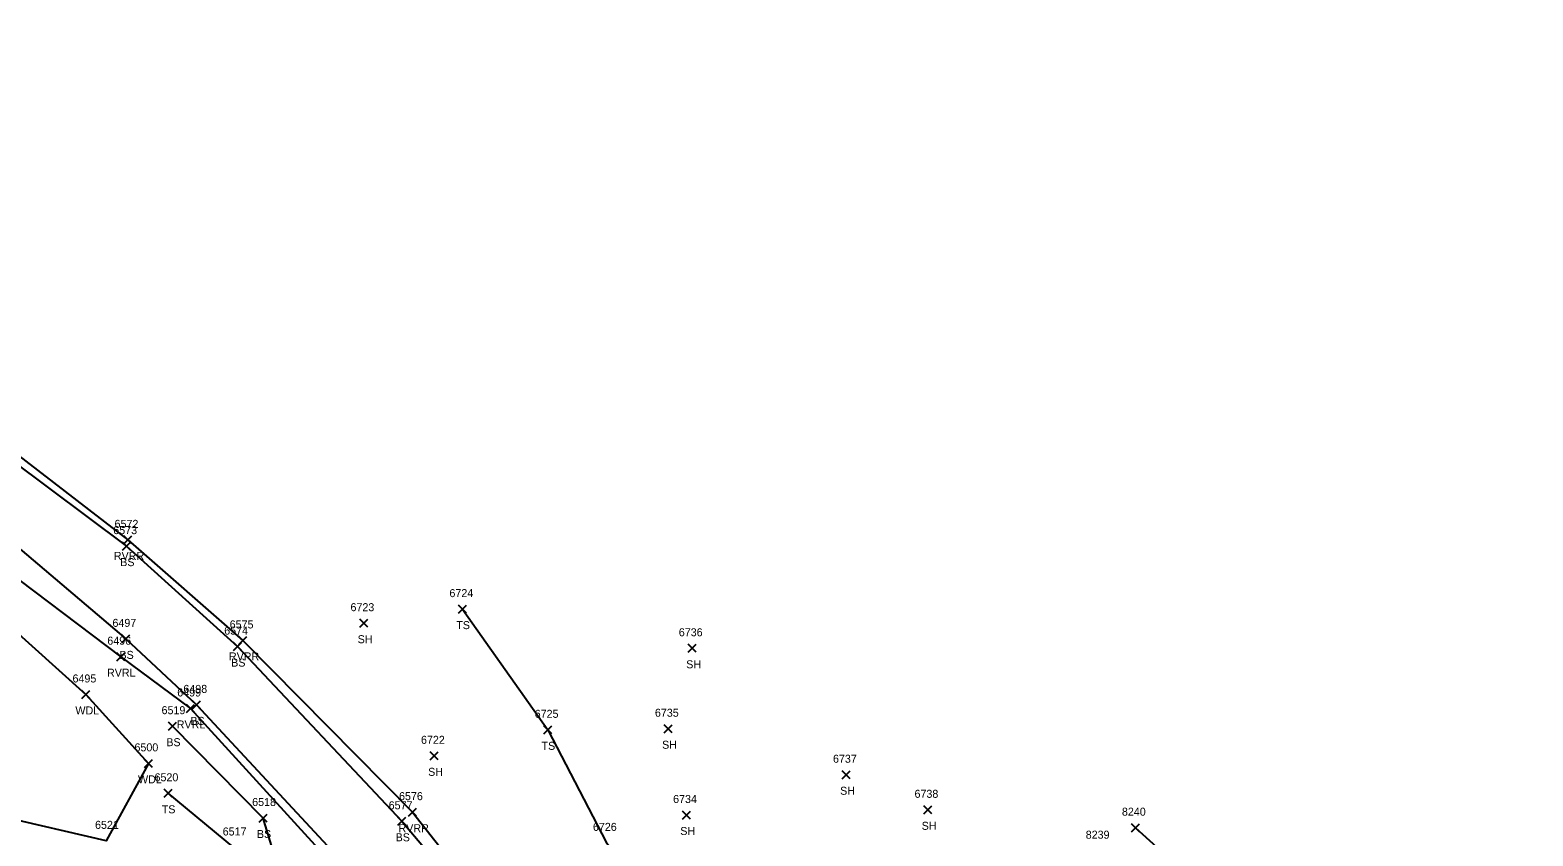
# Model space of a CAD drawing. Extents: x 1588028 to 1589597, y 137576 to 138176.
# Drawn here: x 1588774.4 to 1589149.9, y 137969.2 to 138170.6 of the extents above; entities that cross this region are included whole.
import ezdxf

# ---------------------------------------------------------------- set-up
doc = ezdxf.new("R2010")
doc.units = 0
for name, color, linetype in [('D_I', 7, 'Continuous'), ('L_A', 7, 'Continuous'), ('L_I', 7, 'Continuous'), ('L_TIC', 7, 'Continuous'), ('LAWA', 7, 'Continuous'), ('LAWE', 7, 'Continuous'), ('LELB', 7, 'Continuous')]:
    doc.layers.add(name, color=color, linetype=linetype)

msp = doc.modelspace()

# ---------------------------------------------------------------- linework, layer by layer
at = {"layer": 'L_TIC'}
for points in [[(1588797.46, 138040.61), (1588799.46, 138042.61)], [(1588799.46, 138040.61), (1588797.46, 138042.61)], [(1588797.8, 138042.18), (1588799.8, 138044.18)], [(1588799.8, 138042.18), (1588797.8, 138044.18)], [(1588881.47, 138024.87), (1588883.47, 138026.87)], [(1588883.47, 138024.87), (1588881.47, 138026.87)], [(1588856.75, 138021.35), (1588858.75, 138023.35)], [(1588858.75, 138021.35), (1588856.75, 138023.35)], [(1588797.27, 138017.43), (1588799.27, 138019.43)], [(1588799.27, 138017.43), (1588797.27, 138019.43)], [(1588825.19, 138015.5), (1588827.19, 138017.5)], [(1588827.19, 138015.5), (1588825.19, 138017.5)], [(1588826.56, 138017.04), (1588828.56, 138019.04)], [(1588828.56, 138017.04), (1588826.56, 138019.04)], [(1588938.84, 138015.08), (1588940.84, 138017.08)], [(1588940.84, 138015.08), (1588938.84, 138017.08)], [(1588796.04, 138012.98), (1588798.04, 138014.98)], [(1588798.04, 138012.98), (1588796.04, 138014.98)], [(1588787.28, 138003.54), (1588789.28, 138005.54)], [(1588789.28, 138003.54), (1588787.28, 138005.54)], [(1588813.47, 138000.04), (1588815.47, 138002.04)], [(1588815.47, 138000.04), (1588813.47, 138002.04)], [(1588814.99, 138000.93), (1588816.99, 138002.93)], [(1588816.99, 138000.93), (1588814.99, 138002.93)], [(1588808.98, 137995.61), (1588810.98, 137997.61)], [(1588810.98, 137995.61), (1588808.98, 137997.61)], [(1588902.77, 137994.7), (1588904.77, 137996.7)], [(1588904.77, 137994.7), (1588902.77, 137996.7)], [(1588932.82, 137994.97), (1588934.82, 137996.97)], [(1588934.82, 137994.97), (1588932.82, 137996.97)], [(1588874.37, 137988.2), (1588876.37, 137990.2)], [(1588876.37, 137988.2), (1588874.37, 137990.2)], [(1588802.93, 137986.32), (1588804.93, 137988.32)], [(1588804.93, 137986.32), (1588802.93, 137988.32)], [(1588977.32, 137983.47), (1588979.32, 137985.47)], [(1588979.32, 137983.47), (1588977.32, 137985.47)], [(1588807.87, 137978.84), (1588809.87, 137980.84)], [(1588809.87, 137978.84), (1588807.87, 137980.84)], [(1588868.93, 137974.12), (1588870.93, 137976.12)], [(1588870.93, 137974.12), (1588868.93, 137976.12)], [(1588937.37, 137973.41), (1588939.37, 137975.41)], [(1588939.37, 137973.41), (1588937.37, 137975.41)], [(1588997.68, 137974.71), (1588999.68, 137976.71)], [(1588999.68, 137974.71), (1588997.68, 137976.71)], [(1588831.61, 137972.66), (1588833.61, 137974.66)], [(1588833.61, 137972.66), (1588831.61, 137974.66)], [(1588866.28, 137971.84), (1588868.28, 137973.84)], [(1588868.28, 137971.84), (1588866.28, 137973.84)], [(1589049.56, 137970.24), (1589051.56, 137972.24)], [(1589051.56, 137970.24), (1589049.56, 137972.24)]]:
    msp.add_lwpolyline(points, dxfattribs=at)
at = {"layer": 'LAWA'}
for points in [[(1588762.05, 138028.09), (1588788.28, 138004.54), (1588803.93, 137987.32), (1588793.35, 137967.95), (1588766.76, 137974.1)], [(1589050.56, 137971.24), (1589083.91, 137941.07), (1589116.19, 137904.57), (1589140.2, 137894.13), (1589149.91, 137879.08)]]:
    msp.add_lwpolyline(points, dxfattribs=at)
at = {"layer": 'LAWE'}
for points in [[(1588434.56, 138062.89), (1588458.47, 138076.79), (1588495.54, 138110.89), (1588517.72, 138151.17), (1588540.38, 138168.38), (1588562.32, 138170.6), (1588586.16, 138148.71), (1588635.49, 138130.01), (1588676.05, 138127.99), (1588706.09, 138118.66), (1588727.82, 138096.85), (1588770.39, 138065.1), (1588798.8, 138043.18), (1588827.56, 138018.04), (1588869.93, 137975.12), (1588899.99, 137936.94), (1588912.08, 137921.5), (1588926.82, 137898.29), (1588932.86, 137884.09), (1588938.83, 137878.76)], [(1588441.02, 138044.54), (1588465.05, 138060.11), (1588492.43, 138083.39), (1588521.86, 138113.88), (1588530.72, 138143.54), (1588545.57, 138151.23), (1588554.85, 138142.99), (1588577.1, 138115.96), (1588614.25, 138110.98), (1588643.88, 138111.05), (1588664.41, 138106.89), (1588688.53, 138102.18), (1588718.75, 138082.48), (1588743.28, 138056.23), (1588764.53, 138038.44), (1588797.04, 138013.98), (1588814.47, 138001.04), (1588852.47, 137959.37), (1588883.95, 137928.09), (1588897.47, 137912.79), (1588913.44, 137894.45), (1588920.69, 137884.16), (1588921.99, 137878.45)]]:
    msp.add_lwpolyline(points, dxfattribs=at)
at = {"layer": 'LELB'}
for points in [[(1588682.05, 138125.09), (1588705.48, 138117.82), (1588727.76, 138095.08), (1588769.43, 138063.36), (1588798.46, 138041.61), (1588826.19, 138016.5), (1588867.28, 137972.84), (1588898.61, 137935.76), (1588911.42, 137921.16), (1588925.66, 137898.09), (1588931.8, 137883.5), (1588937.54, 137876.95)], [(1588667.09, 138110.74), (1588688.84, 138110.6), (1588719.17, 138088.33), (1588744.4, 138063.38), (1588766.27, 138045.61), (1588798.27, 138018.43), (1588815.99, 138001.93), (1588854.1, 137960.89), (1588885.58, 137929.53), (1588899.45, 137912.94)], [(1588882.47, 138025.87), (1588903.77, 137995.7), (1588918.38, 137967.44), (1588937.02, 137945.26), (1588958.03, 137927.86)], [(1588879.77, 137910.36), (1588853.42, 137914.24), (1588857.54, 137933.72), (1588843.04, 137939.37), (1588832.61, 137973.66), (1588809.98, 137996.61)], [(1588837.96, 137941.54), (1588825.25, 137966.29), (1588808.87, 137979.84)]]:
    msp.add_lwpolyline(points, dxfattribs=at)

# ---------------------------------------------------------------- texts
at = {"layer": 'D_I'}
msp.add_text('8239', height=2, dxfattribs=at).set_placement((1589038.16, 137968.49))
at = {"layer": 'L_A'}
for s, p in [('RVRR', (1588795.31, 138038.18)), ('BS', (1588796.9, 138036.61)), ('TS', (1588880.88, 138020.87)), ('SH', (1588856.23, 138017.35)), ('BS', (1588796.71, 138013.43)), ('RVRR', (1588824.07, 138013.04)), ('BS', (1588824.63, 138011.5)), ('SH', (1588938.33, 138011.08)), ('RVRL', (1588793.6, 138008.98)), ('WDL', (1588785.7, 137999.54)), ('RVRL', (1588811.03, 137996.04)), ('BS', (1588814.43, 137996.93)), ('BS', (1588808.42, 137991.61)), ('TS', (1588902.18, 137990.7)), ('SH', (1588932.31, 137990.97)), ('SH', (1588873.85, 137984.2)), ('WDL', (1588801.35, 137982.32)), ('SH', (1588976.8, 137979.47)), ('TS', (1588807.28, 137974.84)), ('RVRR', (1588866.44, 137970.12)), ('SH', (1588936.85, 137969.41)), ('SH', (1588997.17, 137970.71)), ('BS', (1588831.05, 137968.66)), ('BS', (1588865.72, 137967.84))]:
    msp.add_text(s, height=2, dxfattribs=at).set_placement(p)
at = {"layer": 'L_I'}
for s, p in [('6573', (1588795.16, 138044.61)), ('6572', (1588795.49, 138046.18)), ('6724', (1588879.16, 138028.87)), ('6723', (1588854.44, 138025.35)), ('6497', (1588794.96, 138021.43)), ('6574', (1588822.89, 138019.5)), ('6575', (1588824.25, 138021.04)), ('6736', (1588936.48, 138019.08)), ('6496', (1588793.68, 138016.98)), ('6495', (1588784.98, 138007.54)), ('6499', (1588811.15, 138004.04)), ('6498', (1588812.68, 138004.93)), ('6519', (1588807.23, 137999.61)), ('6725', (1588900.47, 137998.7)), ('6735', (1588930.51, 137998.97)), ('6722', (1588872.06, 137992.2)), ('6500', (1588800.46, 137990.32)), ('6737', (1588975.01, 137987.47)), ('6520', (1588805.47, 137982.84)), ('6518', (1588829.87, 137976.66)), ('6576', (1588866.57, 137978.12)), ('6734', (1588935.06, 137977.41)), ('6738', (1588995.38, 137978.71)), ('6577', (1588863.98, 137975.84)), ('8240', (1589047.21, 137974.24)), ('6521', (1588790.61, 137970.95)), ('6517', (1588822.51, 137969.29)), ('6726', (1588915.02, 137970.44))]:
    msp.add_text(s, height=2, dxfattribs=at).set_placement(p)

doc.saveas('drawing.dxf')
